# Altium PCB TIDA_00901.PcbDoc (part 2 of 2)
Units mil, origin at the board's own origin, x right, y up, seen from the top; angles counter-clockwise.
Board outline 2500 x 2500 mil, 4 copper layers (Top Layer, GND, PVDD, Bottom Layer), stack 59.2 mil thick; 113 components, 73 nets, 335 pads, 307 vias.
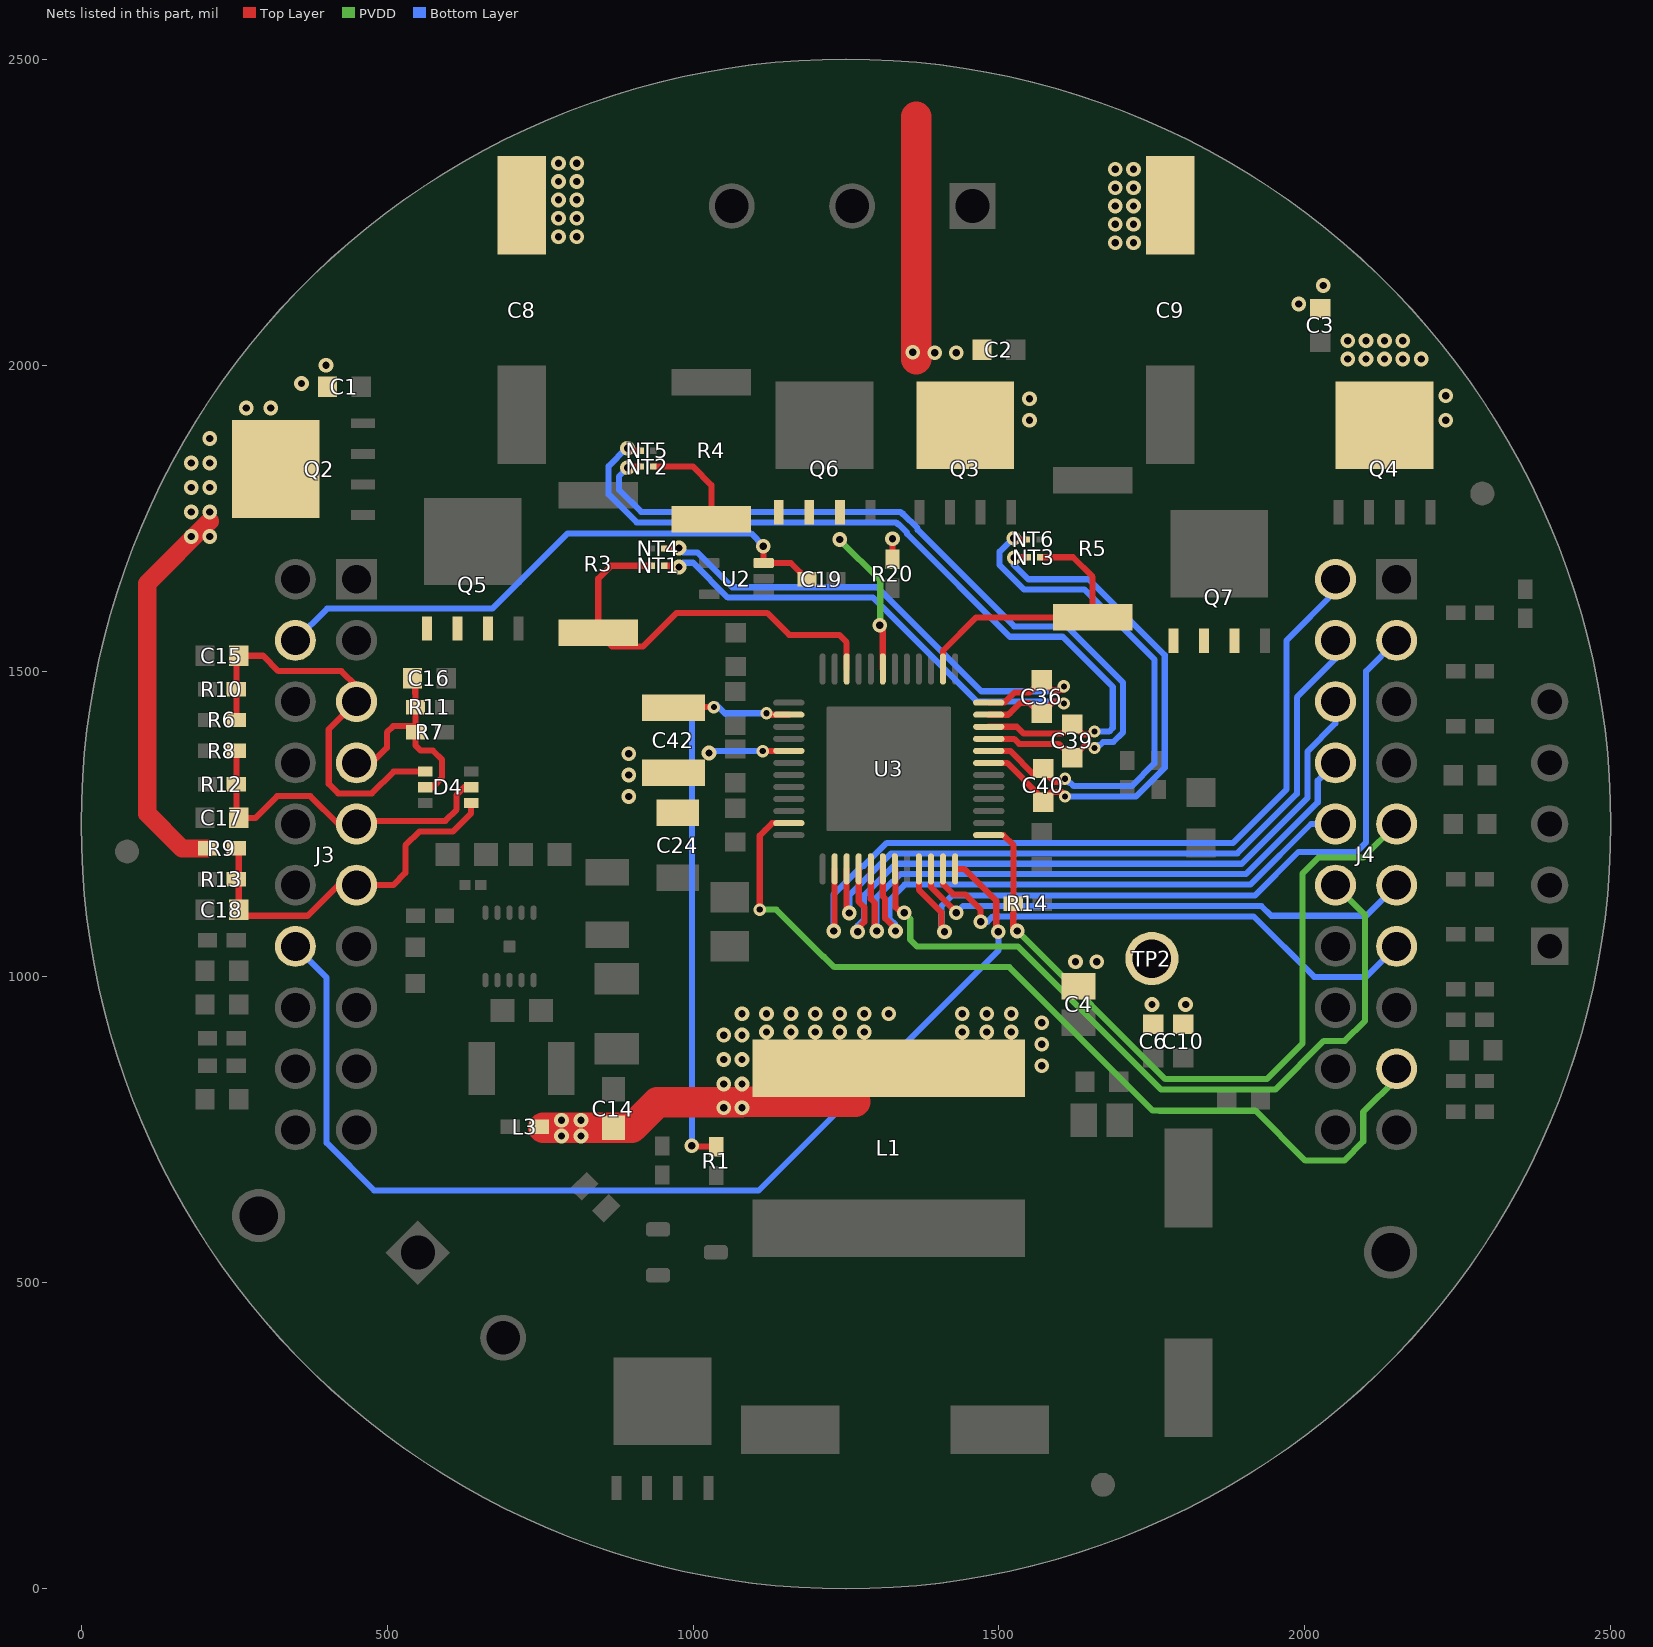
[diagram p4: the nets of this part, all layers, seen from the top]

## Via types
v1: diameter 24, hole 12, Top Layer to Bottom Layer, tented both sides, 267 vias
v2: diameter 19.68, hole 7.87, Top Layer to Bottom Layer, 29 vias
v3: diameter 20, hole 10, Top Layer to Bottom Layer, tented both sides, 11 vias

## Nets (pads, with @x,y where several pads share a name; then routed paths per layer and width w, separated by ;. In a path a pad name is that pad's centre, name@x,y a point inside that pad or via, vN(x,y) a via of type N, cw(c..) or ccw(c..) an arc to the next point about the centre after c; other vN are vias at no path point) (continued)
PVDD: C1.1 C2.1 C3.1 C4.1 C6.1 C8.1 C9.1 C10.1 C14.1 C24.2 C42.2 L1.2 L3.1 Q2.5 Q3.5 Q4.5 R9.2 R20.2 TP2.1 U3.41 | length 1808.1
  Top Layer w10: v3(1114,1369) 1114.53,1369.53 U3.41@1156.61,1369.53 ; R20.2@1326,1682.62 v1(1326,1716)
  Top Layer w20: 1265.09,796 L1.2@1320,850.91
  Top Layer w30: R9.2@206.38,1210 165,1210 108,1267 108,1643 210,1745
  Top Layer w50: L3.1@755.62,753.5 C14.1@870,753.5 900.07,753.5 941.56,795 1079,795 1080,796 1265.09,796 ; 1365,2010 1365,2405.67
  Bottom Layer w10: v1(1026,1366) 1029,1369 v3(1114,1369)
  other v1: 785,740 817,740 785,766 817,766 1050,786 1080,786 1050,825 1080,825 1570,855 1050,865 1080,865 1570,890 1050,905 1080,905 1120,910 1160,910 1200,910 1240,910 1280,910 1440,910 1480,910 1520,910 1570,925 1080,940 1120,940 1160,940 1200,940 1240,940 1280,940 1320,940 1440,940 1480,940 1520,940 1750,955 1805,955 1625,1025 1660,1025 895,1295 895,1330 895,1365 180,1720 210,1720 180,1760 210,1760 180,1800 210,1800 180,1840 210,1840 210,1880 1550,1910 2230,1910 270,1930 310,1930 1550,1945 2230,1950 360,1970 400,2000 2070,2010 2100,2010 2130,2010 2160,2010 2190,2010 1395,2020 1430,2020 1359,2021 2070,2040 2100,2040 2130,2040 2160,2040 1990,2100 2030,2130 1690,2200 1720,2200 780,2210 810,2210 1690,2230 1720,2230 780,2240 810,2240 1690,2260 1720,2260 780,2270 810,2270 1690,2290 1720,2290 780,2300 810,2300 1690,2320 1720,2320 780,2330 810,2330
PWM_AH: J4.2 U3.2 | length 1349.9
  Top Layer w10: v1(1230,1075) 1231.42,1076.42 U3.2@1231.42,1176.61
  Bottom Layer w10: v1(1230,1075) 1230,1135 1276.4,1181.4 1279.27,1181.4 1316.88,1219 1882.58,1219 1970,1306.42 1970,1550 2050,1630 J4.2@2050,1650
PWM_AL: J4.4 U3.3 | length 1186.3
  Top Layer w10: U3.3@1251.1,1176.61 1251.1,1108.9 v1(1255.55,1104.45) v1@1260,1100
  Bottom Layer w10: v1(1255.55,1104.45) 1255.55,1133.63 1323.92,1202 1889.62,1202 1987,1299.38 1987,1457 2050,1520 J4.4@2050,1550
PWM_BH: J4.6 U3.4 | length 1141.9
  Top Layer w10: v1(1268.94,1074) 1268.94,1078.94 1280,1090 1280,1113.94 1270.79,1123.15 U3.4@1270.79,1176.61
  Bottom Layer w10: v1(1268.94,1074) 1268.94,1083.9 1279.55,1094.51 1279.55,1133.59 1330.96,1185 1896.66,1185 2004,1292.34 2004,1368.3 2050,1414.3 J4.6@2050,1450
PWM_BL: J4.8 U3.5 | length 1026.1
  Top Layer w10: U3.5@1290.47,1176.61 1290.47,1127.51 1297,1120.98 1297,1082.96 1296.55,1082.51 v1@1296.55,1070.45
  Bottom Layer w10: v1(1300,1075) 1300,1130 1326.28,1156.28 1327.24,1156.28 1338.96,1168 1903.7,1168 2021,1285.3 2021,1321 J4.8@2050,1350
PWM_CH: J4.10 U3.6 | length 945.8
  Top Layer w10: U3.6@1310.16,1176.61 1310.16,1131.87 1314,1128.02 1314,1096 1331,1079 v1(1331,1075)
  Bottom Layer w10: v1(1331,1075) 1331,1085.06 1321,1095.06 1321,1124.94 1331,1134.94 1331,1136 1346,1151 1911,1151 2010,1250 J4.10@2050,1250
PWM_CL: J4.12 U3.7 | length 1256.7
  Top Layer w10: U3.7@1329.84,1176.61 1331,1175.46 1331,1114 v1@1340,1105
  PVDD w10: v1(1345,1105) 1355,1095 1355,1061 1366,1050 1530.96,1050 1764.96,816 1951.7,816 2031.17,895.46 2065.46,895.46 2098,928 2098,1102 J4.12@2050,1150
PWRGD: J4.9 R14.1 U3.13 | length 1247.5
  Top Layer w10: U3.13@1483.39,1231.73 1507.27,1231.73 1524,1215 1524,1120.62 R14.1@1523.38,1120 1523.38,1081.62 v1(1530,1075)
  PVDD w10: v1(1530,1075) 1530,1073 1532,1073 1772,833 1938,833 1996,891 1996,1169.02 2022.44,1195.46 2095.46,1195.46 J4.9@2150,1250
S1_N: C36.1 NT1.1 U3.23 | length 900.1
  Top Layer w10: NT1.1@953,1672 975,1672 v1(977,1670) ; U3.23@1483.39,1428.58 1514.67,1428.58 1516.99,1430.9 1517.79,1430.9 1534.89,1448 1549.44,1448 C36.1@1570,1427.44 ; C36.1@1570,1430.44 1589.06,1449.5 1603.5,1449.5 v3(1606,1447)
  Bottom Layer w10: v1(977,1670) 984,1677 1000,1677 1057,1620 1294.21,1620 1464.21,1450 1603,1450 v3(1606,1447)
S1_P: C36.2 NT4.1 U3.24 | length 903.3
  Top Layer w10: NT4.1@953,1700 976,1700 v1(977,1701) ; U3.24@1483.39,1448.27 1508.73,1448.27 1525.46,1465 1550,1465 1553.24,1468.24 1567.56,1482.56 C36.2@1570,1482.56 ; C36.2@1570,1485.56 1586.56,1469 1606,1469 v3(1606,1475)
  Bottom Layer w10: v1(977,1701) 984,1694 1007.04,1694 1064.04,1637 1301.25,1637 1471.25,1467 1594.89,1467 1596.89,1469 1597,1469 1603,1475 v3(1606,1475)
S2_N: C39.1 NT2.1 U3.21 | length 1356.1
  Top Layer w10: v1(893,1832) 895,1834 NT2.1@915,1834 ; U3.21@1483.39,1389 U3.21@1483.39,1389.21 1524.75,1389.21 1532.96,1381 1597.44,1381 C39.1@1620,1358.44 1639.06,1377.5 1652.5,1377.5 v3(1656,1374)
  Bottom Layer w10: v1@891.5,1833.5 v1(893,1832) 879,1818 879,1796 915,1760 1339,1760 1342,1757 1342.98,1757 1367,1732.98 1367,1731 1525,1573 1611.04,1573 1703,1481.04 1703,1399.96 1687.04,1384 1670.11,1384 1665.11,1379 1661,1379 v3(1656,1374)
S2_P: C39.2 NT5.1 U3.22 | length 1360.7
  Top Layer w10: v1(893,1864) 897,1860 NT5.1@915,1860 ; U3.22@1483.39,1408.9 1529.1,1408.9 1540,1398 1604.44,1398 C39.2@1620,1413.56 1637.56,1396 1651,1396 v3(1656,1401)
  Bottom Layer w10: v1(893,1864) 891.06,1864 862,1834.94 862,1788.96 907.96,1743 1331.96,1743 1334.96,1740 1335.94,1740 1350,1725.94 1350,1723.96 1517.96,1556 1604,1556 1686,1474 1686,1407 1680,1401 v3(1656,1401)
S3_N: C40.1 NT3.1 U3.19 | length 876
  Top Layer w10: U3.19@1483.39,1349.84 1513.27,1349.84 1567,1296.11 1567,1290.44 C40.1@1572,1285.44 1577,1290.44 1577,1293.5 1585.5,1302 1603,1302 1608,1297 v3(1608,1295) ; v1(1525,1685) 1526,1686 NT3.1@1547,1686
  Bottom Layer w10: v1(1525,1685) 1524,1684 1524,1674.04 1548.04,1650 1647.04,1650 1771,1526.04 1771,1341.96 1724.04,1295 v3(1608,1295)
S3_P: C40.2 NT6.1 U3.20 | length 888.1
  Top Layer w10: U3.20@1483.39,1369.53 1518.47,1369.53 1558,1330 1561.44,1330 C40.2@1572,1340.56 1577,1335.56 1577,1332.5 1590.5,1319 1603,1319 v3(1608,1324) ; v1(1524,1717) 1526,1715 NT6.1@1546,1715
  Bottom Layer w10: v1(1524,1717) 1523.06,1717 1501,1694.94 1501,1673 1541,1633 1640,1633 1754,1519 1754,1349 1717,1312 1622.11,1312 1617.11,1317 1615,1317 v3(1608,1324)
SCLK: J3.14 U3.12 | length 1813.8
  Top Layer w10: U3.12@1428.27,1176.61 1443.39,1176.61 1495.63,1124.37 1495.63,1079.37 1495,1078.74 1499,1074.74 v1@1498.26,1074 ; v1@1494.26,1070 v1@1498.26,1074 ; v1(1499,1074) v1@1498.26,1074
  Bottom Layer w10: J3.14@350,1050 401,999 401,729 479,651 1107.04,651 1397,940.96 ; 1397,941 1499,1043 v1(1499,1074)
SCS: J4.3 U3.9 | length 1251.7
  Top Layer w10: U3.9@1369.21,1176.61 1369.21,1142.79 1406,1106 1406,1079 v1(1411,1074)
  Bottom Layer w10: v1(1411,1074) 1406,1079 1406,1115.92 1423.08,1133 1918,1133 1989.54,1204.54 2084.54,1204.54 2100,1220 2100,1500 J4.3@2150,1550
SDI: J4.11 U3.10 | length 840.5
  Top Layer w10: U3.10@1388.9,1176.61 1388.9,1147.14 v1@1423,1113.04 ; v1@1423,1113 1430,1106 v1(1430,1105)
  Bottom Layer w10: v1(1430,1105) 1441,1116 1929,1116 1945,1100 2100,1100 J4.11@2150,1150
SDO: J4.13 U3.11 | length 869.2
  Top Layer w10: U3.11@1408.58,1176.61 1408.58,1151.5 1425.08,1135 1445,1135 1470,1110 v1(1470,1090)
  Bottom Layer w10: v1(1470,1090) 1481.06,1090 1490.06,1099 1916,1099 2015,1000 2100,1000 J4.13@2150,1050
SL_A: NT1.2 Q5.1 Q5.2 Q5.3 R3.2 U3.34 | length 686.7
  Top Layer w10: NT1.2@933,1672 866,1672 845,1651 R3.2@845,1562.8 867.8,1540 918,1540 973,1595 1120.94,1595 1156.94,1559 1238.98,1559 1251.1,1546.87 U3.34@1251.1,1503.39
SL_B: NT2.2 Q6.1 Q6.2 Q6.3 R4.2 U3.31 | length 404.4
  Top Layer w10: NT2.2@935,1834 1000,1834 1030,1804 R4.2@1030,1747.8 ; U3.31@1310.16,1503.39 v1@1310.16,1568.84
  PVDD w10: v1(1240,1715) 1240,1714 1306,1648 1306,1579.96 1310.96,1575 v1(1305,1575)
SL_C: NT3.2 Q7.1 Q7.2 Q7.3 R5.2 U3.26 | length 462.5
  Top Layer w10: U3.26@1408.58,1503.39 1408.58,1533.58 1462.8,1587.8 R5.2@1653,1587.8 1653,1654 1621,1686 NT3.2@1567,1686
TEMP: C19.1 J3.4 U2.3 | length 956.4
  Top Layer w10: v1(1115,1704) 1115.29,1703.71 U2.3@1115.29,1676.59 1159.79,1676.59 C19.1@1186.38,1650
  Bottom Layer w10: J3.4@350,1550 402,1602 672,1602 795,1725 1095,1725 1115,1705 v1(1115,1704)
VCPH: C42.1 R1.1 U3.38 | length 985
  Top Layer w10: C42.1@964,1441.15 1033.85,1441.15 v3(1034,1441) ; v1(998,724) 999.38,722.62 R1.1@1038,722.62 ; v3(1120,1431) v3@1120,1435 ; v3@1122.42,1428.58 U3.38@1156.61,1428.58
  Bottom Layer w10: v1(998,724) 998,1422 1017,1441 v3(1034,1441) 1038,1445 1053,1430 1054,1431 v3(1120,1431)
VSEN_A: C15.1 D4.1 J3.5 R6.1 R10.2 | length 677.4
  Top Layer w10: R6.1@253.62,1420 253.62,1521.06 C15.1@257.56,1525 297.44,1525 322.44,1500 425,1500 450,1475 J3.5@450,1450 404.54,1404.54 404.54,1315.46 420,1300 475,1300 510.59,1335.59 D4.1@562.6,1335.59
VSEN_B: C16.1 D4.2 J3.7 R7.1 R11.2 | length 355.7
  Top Layer w10: J3.7@450,1350 475,1350 499.61,1374.61 499.61,1399.61 510,1410 R7.1@546.38,1410 ; C16.1@546,1482 546.22,1441 R7.1@546.38,1410 ; D4.2@562.6,1310 574,1310 579.32,1315.32 579.38,1315.32 586.41,1322.35 586.41,1322.41 590,1326 590,1355 575,1370 555,1370 546.38,1378.62 R7.1@546.38,1400 R7.1@546.38,1410
VSEN_C: C17.1 D4.5 J3.9 R8.1 R12.2 | length 563.9
  Top Layer w10: R8.1@253.62,1370 253.62,1263.94 C17.1@257.56,1260 285,1260 320.46,1295.46 374.54,1295.46 420,1250 J3.9@450,1250 455,1255 595,1255 613.59,1273.59 613.59,1297.65 620.62,1304.68 620.68,1304.68 626,1310 D4.5@637.4,1310
VSEN_PVDD: C18.1 D4.4 J3.11 R9.1 R13.2 | length 588.3
  Top Layer w10: R9.1@253.62,1210 257.56,1206.06 C18.1@257.56,1110 267.56,1100 370,1100 420,1150 J3.11@450,1150 510,1150 530,1170 530,1215 553,1238 608,1238 637.4,1267.4 637.4,1274.41
WAKE: J4.17 U3.47 | length 1487.7
  Top Layer w10: v3(1109,1110) 1109,1230.96 1118,1239.96 1125.03,1247 1129.46,1251.42 U3.47@1156.61,1251.42
  PVDD w10: v3(1109,1110) 1136,1110 1213,1033 1213.96,1033 1230.96,1016 1516.88,1016 1750.88,782 1762,782 1762.7,781.3 1919.49,781.3 2000.79,700 2064.3,700 2095.46,731.17 2095.46,779.46 2150,834 J4.17@2150,850
pads on no net: FID1.1 FID2.1 FID3.1 J3.1 J3.8 J3.10 J3.12 J3.16 J3.18 J3.19 J3.20 J4.7 J4.18 J4.19 J4.20 U4.6

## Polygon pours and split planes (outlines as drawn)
MOT_A on Bottom Layer "Bottom Layer-No Net" (solid, remove dead copper, pour order 9): 920,2330 1160,2330 1160,2130 930,1900 860,1900 820,1900 770,1850 770,1625 499.21,1625 499.21,1685.79 475,1710 270,1710 270,1940 660,2330
MOT_C on Bottom Layer "Bottom Layer-No Net 1" (solid, remove dead copper, pour order 10): 1390,2330 1810,2330 1835,2305 2175,1965 2175,1710 2035,1710 1995,1670 1995,1575 1705,1575 1700,1580 1640,1640 1640,1820 1640,1825 1390,2075
GND on Bottom Layer "PVDD-No Net" (solid, remove dead copper, pour order 14): 149,1840 202.77,1920.47 215,1950 244,1992 278,2035 315,2080 405,2172 490,2243 555.54,2289.34 665,2356 795,2415 909,2453 979,2470 1099,2491 1179.88,2498.53 1279,2500 1346,2497 1447,2485 1528.26,2469.14 1629.6,2440.97 1710,2412 1792.57,2376.65 1858,2343 1977,2268 2099,2173 2182.42,2083.26 2237,2019 2314,1909 2384,1777 2451.62,1596.18 2480,1477 2497,1338 2498.53,1179.88 2492,1098 2471,978 2405.3,771.46 2344.46,645.11 2269.85,526.38 2197,435 2108.75,341.67 1973.62,230.15 1861,160 1752,105 1625,57 1493.86,24.02 1390.01,7.37 1337,3 1172,2 1040.53,17.18 903.82,48.38 748,105 665,146 526.38,230.15 443.53,294.95 334,398 263,483 166,627 111,727 59.03,870.4 28,989 7.37,1109.99 0,1263 24.02,1493.86 48.38,1596.18 86,1707 139.44,1823.73
PVDD on Top Layer "Top Layer-No Net" (solid, remove dead copper, pour order 8): 61.08,1640 98,1736 123.35,1792.57 169,1878 223,1963 272.33,2029.67 349,2117 391.25,2158.33 489,2242 547,2284 676.27,2360.56 771.46,2405.3 870.4,2440.97 957,2466 1040.53,2482.82 1161,2496 1274,2501 1371,2495 1509,2474 1647,2437 1752,2397 1885.09,2326.64 1964,2276 2024,2232 2108.75,2158.33 2145,2124 2198,2065 2260,1986 2308.82,1915.3 2352,1841 2367,1809 1995,1810 1995,2070 1885,2180 1665,2180 960,2180 865.5,2117 615,2117 615,1640
GND on Top Layer "PVDD-No Net" (solid, remove dead copper, pour order 13): 149,1840 202.77,1920.47 215,1950 244,1992 278,2035 315,2080 405,2172 490,2243 555.54,2289.34 665,2356 795,2415 909,2453 979,2470 1099,2491 1179.88,2498.53 1279,2500 1346,2497 1447,2485 1528.26,2469.14 1629.6,2440.97 1710,2412 1792.57,2376.65 1858,2343 1977,2268 2099,2173 2182.42,2083.26 2237,2019 2314,1909 2384,1777 2451.62,1596.18 2480,1477 2497,1338 2498.53,1179.88 2492,1098 2471,978 2405.3,771.46 2344.46,645.11 2269.85,526.38 2197,435 2108.75,341.67 1973.62,230.15 1861,160 1752,105 1625,57 1493.86,24.02 1390.01,7.37 1337,3 1172,2 1040.53,17.18 903.82,48.38 748,105 665,146 526.38,230.15 443.53,294.95 334,398 263,483 166,627 111,727 59.03,870.4 28,989 7.37,1109.99 0,1263 24.02,1493.86 48.38,1596.18 86,1707 139.44,1823.73
PVDD on PVDD "PVDD-No Net" (solid, remove dead copper, pour order 12): 149,1840 202.77,1920.47 215,1950 244,1992 278,2035 315,2080 405,2172 490,2243 555.54,2289.34 665,2356 795,2415 909,2453 979,2470 1099,2491 1179.88,2498.53 1279,2500 1346,2497 1447,2485 1528.26,2469.14 1629.6,2440.97 1710,2412 1792.57,2376.65 1858,2343 1977,2268 2099,2173 2182.42,2083.26 2237,2019 2314,1909 2384,1777 2451.62,1596.18 2480,1477 2497,1338 2498.53,1179.88 2492,1098 2471,978 2405.3,771.46 2344.46,645.11 2269.85,526.38 2197,435 2108.75,341.67 1973.62,230.15 1861,160 1752,105 1625,57 1493.86,24.02 1390.01,7.37 1337,3 1172,2 1040.53,17.18 903.82,48.38 748,105 665,146 526.38,230.15 443.53,294.95 334,398 263,483 166,627 111,727 59.03,870.4 28,989 7.37,1109.99 0,1263 24.02,1493.86 48.38,1596.18 86,1707 139.44,1823.73
GND on GND "PVDD-No Net" (solid, remove dead copper, pour order 11): 149,1840 202.77,1920.47 215,1950 244,1992 278,2035 315,2080 405,2172 490,2243 555.54,2289.34 665,2356 795,2415 909,2453 979,2470 1099,2491 1179.88,2498.53 1279,2500 1346,2497 1447,2485 1528.26,2469.14 1629.6,2440.97 1710,2412 1792.57,2376.65 1858,2343 1977,2268 2099,2173 2182.42,2083.26 2237,2019 2314,1909 2384,1777 2451.62,1596.18 2480,1477 2497,1338 2498.53,1179.88 2492,1098 2471,978 2405.3,771.46 2344.46,645.11 2269.85,526.38 2197,435 2108.75,341.67 1973.62,230.15 1861,160 1752,105 1625,57 1493.86,24.02 1390.01,7.37 1337,3 1172,2 1040.53,17.18 903.82,48.38 748,105 665,146 526.38,230.15 443.53,294.95 334,398 263,483 166,627 111,727 59.03,870.4 28,989 7.37,1109.99 0,1263 24.02,1493.86 48.38,1596.18 86,1707 139.44,1823.73

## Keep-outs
Keep-Out Layer:
  lines w20: -10,1250 cw(c1250,1250) 1250,2510 cw(c1250,1250) 2510,1250 cw(c1250,1250) 1250,-10 cw(c1250,1250) -10,1250 ; 0,1250 cw(c1250,1250) 1250,2500 cw(c1250,1250) 2500,1250 cw(c1250,1250) 1250,0 cw(c1250,1250) 0,1250
  text ".Layer_Name" at 577,-858.49 h60

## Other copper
Top Layer:
  region net 3.3V: 930,1635 930,1610 1038.69,1610 1049.35,1620.65 1049.35,1685 1010,1685 1010,1669.06 975.94,1635
  region net GND: 2210,900 2270,900 2270,860 2210,860
  region net 3.3V: 1555,1060 1595,1060 1605,1070 1605,1100 1555,1100
  pour cut-out: 880,1643 975,1643 975,1723 880,1723
  pour cut-out: 990,1890 895,1890 895,1810 990,1810
  region net GND: 715,985.17 715,1020 750,1020 750,975 725.17,975
  region net GND: 625,1075 625,1090 655,1120 665,1120 665,1080
  region net GND: 440,1990 440,1935 520,1935 520,1990
  region net NetC33_1: 705,1010 675,1010 675,977.27 625,927.27 625,785 666.81,743.19 720,743.19 720,958.54 705,973.54
  region net 3.3V: 1584.5,1099.5 1540,1055 1215,1055 1185,1085 1185,1235 1130,1235 1130,1106.82 1108.18,1085 850,1085 795,1085 795,988 828,955 920,955 965,1000 1175,1000 1550,1000 1649.5,1099.5
  region net 3.3V: 1875,1260 1740,1260 1725,1275 1725,1325 1695,1325 1695,1195 1645,1145 1555,1145 1555,1095 1840,1095 1875,1130
  region net MOT_C: 2175,1800 1735,1800 1735,1657.06 1792.06,1600 1980,1600 1980,1679.41 2025.59,1725 2175,1725
  region net PVDD: 1375,1810 1340,1845 1340,2050 1340,2113.62 1389.39,2113.62 1453.01,2050 1500,2050 1500,2000 1555,2000 1575,1980 1575,1810
  region net MOT_A: 415.79,1874.21 415.79,1764.21 500,1680 500,1619.21 760.79,1619.21 760.79,1814.21 610.79,1814.21 550.79,1874.21
  region net PVDD: 1036,1380 880,1380 880,1264 909,1235 1036,1235
  region net NetQ1_3: 1010,190 1010,135 1075,135 1075,190
  region net NetQ1_3: 995,695 995,465 1030,465 1065,500 1065,695
  region net NetQ1_1: 980,695 933,695 905,667 905,559.21 919.21,545 980,545
  region net NetD1_2: 865,654.97 832,621.97 832,518 885,465 970.39,465 970.39,535 915,535 895,555 895,625
  region net NetC5_1: 830,445 830,235 855,210 1315,210 1530,425 1810,425 1900,515 1900,830 1735,830 1718,847 1675,847 1675,730 1640,695 1075,695 1075,480 1040,445
  region net NetD1_1: 1000,200 1000,135 817,135 570,382 570,475 785,690 845,690 865,670 820,625 820,230 850,200
  region net PVDD: 1830,1025 1830,907 1728,907 1674,961 1587,961 1585,959 1585,837.72 1517.28,770 1035,770 1035,920 1105,990 1550,990 1640,1080 1775,1080
  region net SL_C: 1580,1610 1580,1560 1680,1460 1840,1460 1915,1535 1915,1575 1785,1575 1750,1610
  region net SL_B: 920,1795 920,1723 1133.77,1723 1177.77,1679 1271,1679 1271,1795 1110,1795
  region net SL_A: 556.06,1595 556.06,1520 620,1520 685,1455 840,1455 928,1543 928,1585 770,1585 725,1540 705,1540 695,1550 695,1595
  pour cut-out: 1580,1810 1580,1610 1725,1610 1725,1810
  pour cut-out: 780,1765 780,1584.76 910,1584.76 910,1765
  pour cut-out: 968.98,1950 968.98,1770 1102,1770 1102,1950
  region net MOT_A: 1175,2330 1020,2330 890,2200 890,2030 1060,2030 1175,2145
  region net MOT_C: 1404.45,2330 1404.45,2118.7 1463.15,2060 1655,2060 1655,2230 1555,2330
  region net MOT_B: 1185,2330 1185,2120 1110,2045 1110,1816 1121,1805 1289,1805 1315,1779 1315,1735 1335,1735 1385,1685 1385,1650 1392,1650 1477,1735 1490,1748 1490,1790 1385,1790 1325,1850 1325,2330
  region net SL_B: 1095,1725 1063.32,1693.32 1016.68,1693.32 980,1730 1095,1730
  text ".Layer_Name" at 577,-858.49 h60
Bottom Layer:
  region net NetC5_1: 960,445 960,235 985,210 1315,210 1530.27,425.27 1809.37,425.27 1899.1,515 1900,515 1900,830 1734.91,830 1715.24,849.67 1712.57,847 1675,847 1675,730 1640,695 1175,695 1075,595 1075,480 1040,445
  region net MOT_B: 1200,2330 1200,2135 1110,2045 1110,1816 1121,1805 1370,1805 1325,1850 1325,2330
  text ".Layer_Name" at 577,-858.49 h60

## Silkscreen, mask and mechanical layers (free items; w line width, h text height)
Top Overlay:
  lines w5: 660,1340 660,1365 745,1365 745,1285 660,1285 ; 660,1345 660,1285 ; 660,1240 660,1285 ; 660,1240 655,1245 665,1245 660,1240
  text "TID-00901" at 805,1015 h60
  text ".PCB_Rev" at 1405,1015 h60
  text ".Layer_Name" at 577,-858.49 h60
Bottom Overlay:
  text ".Layer_Name" at 577,-858.49 h60
Top Paste:
  text ".Layer_Name" at 577,-858.49 h60
Bottom Paste:
  text ".Layer_Name" at 577,-858.49 h60
Top Solder:
  text ".Layer_Name" at 577,-858.49 h60
  text ".Layer_Name" at 577,-858.49 h60
Bottom Solder:
  text ".Layer_Name" at 577,-858.49 h60
Drill Guide:
  text ".Layer_Name" at 577,-858.49 h60
M1 Board Outline:
  circle w10: c1250,1250 r1250
  text ".Layer_Name" at 577,-858.49 h60
M2 Board Dimensions:
  rectangle: 0,-275 125,-150
  rectangle: 125,-400 500,-275
  lines w7: 0,-275 1000,-275 ; 125,-400 125,-150 ; 250,-400 250,-150 ; 500,-400 500,-150 ; 750,-400 750,-150 ; 0,-400 1000,-400 1000,-150 0,-150 0,-400
  text ".Layer_Name" at 577,-858.49 h60
M3 3D STEP Top:
  text ".Layer_Name" at 577,-858.49 h60
M4 3D STEP Bottom:
  text ".Layer_Name" at 577,-858.49 h60
M5 Assembly Top:
  lines w10: -292,-930.17 6308,-930.17 ; -292,-726.83 6310,-726.83 ; -292,-523.5 -292,-1133.5 3713,-1133.5 6310,-1133.5 6310,-523.5 -291.5,-523.5 -291.5,-1133.5 1284,-1133.5 ; 2173,-1133.5 2173,-523.5 ; 3440,-726.83 3440,-523.5 ; 4280,-726.83 4280,-523.5 ; 4902,-1140 4902,-937.17
  text "NOTE: Install J3 and J4 on the BOTTOM side of the board" at 88,3446 h60
  text "COMPONENTS MARKED 'DNP' SHOULD NOT BE POPULATED." at 1153.5,-318.5 h60
  text "ASSEMBLY VARIANT:" at 1153,-434 h60
  text ".VariantName" at 2189,-434 h60
  text "PCB VIEWED FROM TOP SIDE" at -228.5,-655.67 h60
  text "BOARD #:" at 2248,-655.67 h60
  text ".PRJ_Number" at 2793.5,-655.67 h60
  text "REV:" at 3638,-655.67 h60
  text ".PCB_Rev" at 3929.5,-655.67 h60
  text "SVN REV:" at 4476,-655.67 h60
  text ".VersionControl_RevNumber" at 4982,-655.67 h60
  text "TID #:" at 2248,-859 h60
  text ".TID" at 2793.5,-859 h60
  text "PLOT NAME =" at -228.5,-1064.34 h60
  text ".plot_File_Name" at 577,-1064.34 h60
  text "GENERATED    :" at 2250,-1064.34 h60
  text ".Print_Date" at 3119.5,-1064.34 h60
  text ".Print_Time" at 3848.5,-1064.34 h60
  text "TEXAS INSTRUMENTS" at 5113,-1064.34 h60
M6 Assembly Bottom:
  lines w10: -292.5,-727.33 6309.5,-727.33 ; -290.5,-930.67 6309.5,-930.67 ; 1115.5,-1140.5 1115.5,-937.67 ; 1737.5,-727.33 1737.5,-524 ; 2577.5,-727.33 2577.5,-524 ; 3844.5,-1134 3844.5,-524 ; 4733.5,-1134 6309,-1134 6309,-524 -292.5,-524 -292.5,-1134 2304.5,-1134 6309.5,-1134 6309.5,-524
  text "COMPONENTS MARKED 'DNP' SHOULD NOT BE POPULATED." at 6102,-318 h60
  text ".VariantName" at 5058,-434 h60
  text "ASSEMBLY VARIANT:" at 6097,-434 h60
  text ".VersionControl_RevNumber" at 1035.5,-656.17 h60
  text "SVN REV:" at 1541.5,-656.17 h60
  text ".PCB_Rev" at 2088,-656.17 h60
  text "REV:" at 2379.5,-656.17 h60
  text ".PRJ_Number" at 3224,-656.17 h60
  text "BOARD #:" at 3769.5,-656.17 h60
  text "PCB VIEWED FROM BOTTOM SIDE" at 6246,-656.17 h60
  text ".TID" at 3224,-859.5 h60
  text "TID #:" at 3769.5,-859.5 h60
  text "TEXAS INSTRUMENTS" at 904.5,-1064.84 h60
  text ".Print_Time" at 2169,-1064.84 h60
  text ".Print_Date" at 2898,-1064.84 h60
  text "GENERATED    :" at 3767.5,-1064.84 h60
  text ".plot_File_Name" at 5440.5,-1064.84 h60
  text "PLOT NAME =" at 6246,-1064.84 h60
M9 Title Sheet:
  drawing of 57 lines, arcs and shapes, not listed
  text "1" at 739.84,8036.5 h70
  text "2" at 3235.5,8036.5 h70
  text "3" at 5724.84,8036.5 h70
  text "4" at 8231.51,8036.5 h70
  text "5" at 10730.5,8036.5 h70
  text "6" at 13235.5,8036.5 h70
  text "A" at -416.5,6893.5 h70
  text "A" at 14383.5,6893.5 h70
  text "B" at -416.5,4513.5 h70
  text "B" at 14383.5,4513.5 h70
  text "C" at -416.5,2138.5 h70
  text "C" at 14383.5,2138.5 h70
  text "PROJECT TITLE:" at 11343.5,277.5 h45
  text ".PRJ_Title" at 11393.5,144.17 h70
  text "DESIGNED FOR:" at 11343.5,-23.5 h45
  text ".PRJ_Customer" at 11393.5,-163.5 h70
  text "D" at -416.5,-231.5 h70
  text "D" at 14383.5,-231.5 h70
  text "FILE NAME:" at 11343.5,-323.5 h45
  text ".PCB_File_Name_No_Path" at 11393.5,-443.5 h70
  text "Texas Instruments (TI) and/or its licensors do not warrant the accuracy or completeness of this specification" at 6374,-605.34 h45
  text "ENGINEER:" at 11343.5,-613.5 h45
  text "LAYOUT BY:" at 12848.5,-613.5 h45
  text "or any information contained therein. TI and/or its licensors do not warrant that this design will meet" at 6329.01,-718 h45
  text ".PRJ_Engineer" at 11393.5,-768.49 h70
  text ".PCB_Layout" at 12899,-768.49 h70
  text "the specifications, will be suitable for your application or fit for any particular purpose, or will operate in" at 6329.01,-830.67 h45
  text ".Layer_Name" at 577,-858.49 h60
  text "ALTIUM DESIGNER VERSION:" at 12848.5,-923.5 h45
  text "an implementation. TI and/or its licensors do not warrant that the design is production worthy. You should" at 6329.01,-943.33 h45
  text "completely validate and test your design implementation to confirm the system functionality for your application." at 6374,-1056 h45
  text ".print_Scale" at 11393.5,-1056.83 h70
  text ".Application_BuildNumber" at 12899,-1056.83 h70
  text "1" at 739.84,-1263.5 h70
  text "2" at 3235.5,-1263.5 h70
  text "3" at 5724.84,-1263.5 h70
  text "4" at 8231.51,-1263.5 h70
  text "5" at 10730.5,-1263.5 h70
  text "6" at 13235.5,-1263.5 h70
M10 Fab Notes:
  drawing of 189 lines, arcs and shapes, not listed
  text "DESIGN INFORMATION" at 12381.02,6028 h60
  text "MIN. TRACK WIDTH:" at 11736.46,5848 h60
  text "8" at 12832.7,5848 h60
  text "MIL" at 12987.46,5848 h60
  text "MIN. CLEARANCE:" at 11736.46,5716 h60
  text "0.2" at 12772.7,5716 h60
  text "mm" at 12987.46,5716 h60
  text "MIN. VIA PAD SIZE:" at 11736.46,5584 h60
  text "24" at 12802.71,5584 h60
  text "MIL" at 12987.46,5584 h60
  text "0.05mm (2MIL)" at 12431.46,5442.29 h60
  text "MINIMUM ANNULAR RING" at 11407.23,5438 h60
  text "EXTERNAL" at 13139.46,5438 h60
  text "PER" at 11607.23,5320 h60
  text "IPC-D-275 CLASS 2 LEVEL C" at 11827.23,5320 h60
  text "MIL, HOLES" at 13315.46,5207.71 h60
  text "+/-" at 12923,5207 h60
  text "+/-" at 13777,5207 h60
  text "REGISTRATION TOLERANCES:" at 11407.23,5202 h60
  text "METAL" at 12607,5202 h60
  text "5" at 13183.2,5202 h60
  text "3" at 14016.2,5202 h60
  text "MIL" at 14132.46,5202 h60
  text "+/-" at 13777,5089 h60
  text "HOLE SIZE TOLERANCE (UNLESS OTHERWISE SPECIFIED):" at 11407.23,5084 h60
  text "3" at 14016.2,5084 h60
  text "MIL" at 14132.46,5084 h60
  text "MATERIAL:" at 11332.46,4874.54 h60
  text "FR-4 High Tg" at 12318.9,4734.21 h60
  text "FR-408" at 11753.46,4725.64 h60
  text "OTHER" at 13241.46,4725.64 h60
  text "X" at 12164,4722 h60
  text "62 MIL (1.6mm) +/-10%" at 12073.56,4562.92 h60
  text "THICKNESS:" at 11407.23,4558.64 h60
  text "X" at 11945.4,4558.64 h60
  text "OTHER" at 13358.46,4558.64 h60
  text "TOLERANCE:" at 11407.23,4400.64 h60
  text "X" at 12246.53,4400.64 h60
  text "ANSI IPC-6012 TYPE 3 CLASS 2" at 12433.48,4400.64 h60
  text "OTHER +/-" at 12433.46,4244.64 h60
  text "BOW & TWIST:" at 11407.23,4087.64 h60
  text "X" at 12246.53,4087.64 h60
  text "ANSI IPC-6012 TYPE 3 CLASS 2" at 12433.48,4087.64 h60
  text "OTHER +/-" at 12433.46,3929.13 h60
  text "DRILLING:" at 11332.46,3790.64 h60
  text "REFERENCE:" at 11407.23,3673.64 h60
  text "X" at 12055.46,3673.64 h60
  text "AS SHOWN" at 12242.46,3673.64 h60
  text "X" at 12956.46,3673.64 h60
  text "NC_DRILL FILES" at 13093.46,3673.64 h60
  text "PTH MIN COPPER THICKNESS:" at 11407.23,3515.64 h60
  text "X" at 12757.46,3515.64 h60
  text "1MIL" at 12894.46,3515.64 h60
  text "OTHER" at 13391.46,3515.64 h60
  text "BOARD FINISH:" at 11332.46,3356.64 h60
  text "SILKSCREEN:" at 11487.68,3238.64 h60
  text "X" at 12436.46,3238.64 h60
  text "TOP" at 12562.46,3238.64 h60
  text "X" at 12946.46,3238.64 h60
  text "BOTTOM" at 13073.46,3238.64 h60
  text "SILKSCREEN COLOR:" at 11487.68,3071.64 h60
  text "X" at 12435.42,3071.64 h60
  text "WHITE" at 12562.46,3071.64 h60
  text "OTHER" at 13073.46,3071.64 h60
  text "X" at 12566.42,2912.44 h60
  text "GREEN" at 12693.46,2912.44 h60
  text "OTHER" at 13311.46,2912.44 h60
  text "SOLDER RESIST COLOR:" at 11487.68,2901.64 h60
  text "X" at 12566.42,2742.44 h60
  text "MATTE" at 12693.46,2742.44 h60
  text "SEMI-GLOSS" at 13311,2741.8 h60
  text "IMMERSION GOLD (ENIG)" at 12393.46,2553.92 h60
  text "ENEPIG" at 13731,2550.64 h60
  text "SURFACE FINISH:" at 11332.46,2549.64 h60
  text "X" at 12206.51,2549.64 h60
  text "IMM. TIN/SILVER OR EQUIV" at 11662,2392.64 h60
  text "OTHER" at 13093.46,2392.64 h60
  text "ARRAY/PANEL:" at 11332.46,2213.64 h60
  text "CUT AND TRIM PER M1 BOARD OUTLINE" at 12393.46,2209.35 h60
  text "N.C. ROUTE" at 12393.46,2057.64 h60
  text "X" at 13072.46,2057.64 h60
  text "V. SCORE" at 13259.46,2057.64 h60
  text "CERTIFICATION:" at 11332.46,1920.64 h60
  text "MATERIALS AND WORKMANSHIP FOR ALL PCBS" at 12057.46,1920.64 h60
  text "TO MEET OR EXCEED THE REQUIREMENTS OF:" at 12057.46,1822.64 h60
  text "X" at 11683.96,1686.13 h60
  text "ANSI IPC-A-600F CLASS ->" at 11822.96,1686.13 h60
  text "X" at 13462.02,1686.13 h60
  text "2" at 13580.96,1686.14 h60
  text "1" at 13265.96,1684.64 h60
  text "3" at 13934.96,1684.64 h60
  text "X" at 11686.02,1526.64 h60
  text "UL 94V-0" at 11822.96,1526.64 h60
  text "X" at 12498.02,1526.64 h60
  text "RoHS" at 12634.96,1526.64 h60
  text "OTHER" at 13279.36,1526.64 h60
  text "PER ORDER" at 13676.42,1526.64 h60
  text "ADDITIONAL REQUIREMENTS:" at 11332.46,1385.64 h60
  text "MICROSECTION:" at 11407.23,1270.64 h60
  text "YES" at 12312.96,1270.64 h60
  text "REQUIRED" at 13174.46,1114.49 h60
  text "BARE BOARD ELEC. TEST:" at 11407.23,1111.64 h60
  text "NONE" at 12712.96,1111.64 h60
  text "X" at 13047.46,1111.64 h60
  text "PER ORDER" at 13766.46,1111.64 h60
  text "MANUFACTURER'S UL:" at 11407.23,954.64 h60
  text "RAIL" at 12572.96,950.35 h60
  text "METAL" at 13064.77,950.35 h60
  text "X" at 13440,950 h60
  text "SILK" at 13576.46,950.35 h60
  text ".Layer_Name" at 577,-858.49 h60
M11 Gerber Information:
  lines w10: -292,-930.17 6308,-930.17 ; -292,-726.83 6310,-726.83 ; -292,-523.5 -292,-1133.5 3713,-1133.5 6310,-1133.5 6310,-523.5 -291.5,-523.5 -291.5,-1133.5 1284,-1133.5 ; 2173,-1133.5 2173,-523.5 ; 3440,-726.83 3440,-523.5 ; 4280,-726.83 4280,-523.5 ; 4902,-1140 4902,-937.17
  text "ALL ARTWORK VIEWED FROM TOP SIDE" at -228.5,-655.67 h60
  text "BOARD #:" at 2248,-655.67 h60
  text ".PRJ_Number" at 2793.5,-655.67 h60
  text "REV:" at 3638,-655.67 h60
  text ".PCB_Rev" at 3929.5,-655.67 h60
  text "SVN REV:" at 4476,-655.67 h60
  text ".VersionControl_RevNumber" at 4982,-655.67 h60
  text "LAYER NAME =" at -228.5,-858.49 h60
  text "TID #:" at 2248,-859 h60
  text ".TID" at 2793.5,-859 h60
  text "PLOT NAME =" at -228.5,-1064.34 h60
  text ".plot_File_Name" at 577,-1064.34 h60
  text "GENERATED    :" at 2250,-1064.34 h60
  text ".Print_Date" at 3119.5,-1064.34 h60
  text ".Print_Time" at 3848.5,-1064.34 h60
  text "TEXAS INSTRUMENTS" at 5113,-1064.34 h60
M12 Stackup:
  drawing of 295 lines, arcs and shapes, not listed
  text "Layer" at 9760,7800 h60
  text "Name" at 10169.91,7800 h60
  text "Material" at 11109.65,7800 h60
  text "Thickness" at 11969.42,7800 h60
  text "Constant" at 12619.26,7800 h60
  text "Board Layer Stack" at 13189.12,7800 h60
  text "1" at 9760,7680 h60
  text "Top Overlay" at 10169.91,7680 h60
  text "2" at 9760,7560 h60
  text "Top Solder" at 10169.91,7560 h60
  text "Solder Resist" at 11109.65,7560 h60
  text "0.40mil" at 11969.42,7560 h60
  text "3.5" at 12619.26,7560 h60
  text "3" at 9760,7440 h60
  text "Top Layer" at 10169.91,7440 h60
  text "Copper" at 11109.65,7440 h60
  text "2.80mil" at 11969.42,7440 h60
  text "4" at 9760,7320 h60
  text "Dielectric1" at 10169.91,7320 h60
  text "FR-4" at 11109.65,7320 h60
  text "10.00mil" at 11969.42,7320 h60
  text "4.2" at 12619.26,7320 h60
  text "5" at 9760,7200 h60
  text "Signal Layer 1" at 10169.91,7200 h60
  text "Copper" at 11109.65,7200 h60
  text "2.80mil" at 11969.42,7200 h60
  text "6" at 9760,7080 h60
  text "Dielectric 3" at 10169.91,7080 h60
  text "FR-4" at 11109.65,7080 h60
  text "28.00mil" at 11969.42,7080 h60
  text "4.2" at 12619.26,7080 h60
  text "7" at 9760,6960 h60
  text "Signal Layer 2" at 10169.91,6960 h60
  text "Copper" at 11109.65,6960 h60
  text "2.80mil" at 11969.42,6960 h60
  text "8" at 9760,6840 h60
  text "Dielectric 2" at 10169.91,6840 h60
  text "FR-4" at 11109.65,6840 h60
  text "10.00mil" at 11969.42,6840 h60
  text "4.2" at 12619.26,6840 h60
  text "9" at 9760,6720 h60
  text "Bottom Layer" at 10169.91,6720 h60
  text "Copper" at 11109.65,6720 h60
  text "2.80mil" at 11969.42,6720 h60
  text "10" at 9760,6600 h60
  text "Bottom Solder" at 10169.91,6600 h60
  text "Solder Resist" at 11109.65,6600 h60
  text "0.40mil" at 11969.42,6600 h60
  text "3.5" at 12619.26,6600 h60
  text "11" at 9760,6480 h60
  text "Bottom Overlay" at 10169.91,6480 h60
  text ".Layer_Name" at 577,-858.49 h60
M13 Component Bodies Top:
  text ".Layer_Name" at 577,-858.49 h60
M14 Component Bodies Bottom:
  text ".Layer_Name" at 577,-858.49 h60
M15 Courtyards Top:
  text ".Layer_Name" at 577,-858.49 h60
M16 Courtyards Bottom:
  text ".Layer_Name" at 577,-858.49 h60
Drill Drawing:
  circle w1: c3142.72,1571.04 r24.89
  lines w1: 3117.83,650.24 3117.83,662.68 3130.27,675.12 3117.83,687.57 3117.83,700.01 3130.27,700.01 3142.72,687.57 3155.16,700.01 3167.6,700.01 3167.6,687.57 3155.16,675.12 3167.6,662.68 3167.6,650.24 3155.16,650.24 3142.72,662.68 3130.27,650.24 3117.83,650.24 ; 3117.83,812 3130.27,812 3130.27,799.56 3155.16,799.56 3155.16,812 3167.6,812 3167.6,836.89 3155.16,836.89 3155.16,849.33 3130.27,849.33 3130.27,836.89 3117.83,836.89 3117.83,812 ; 3117.83,948.88 3142.72,961.32 3167.6,948.88 3155.16,973.76 3167.6,998.65 3142.72,986.21 3117.83,998.65 3130.27,973.76 3117.83,948.88 ; 3117.83,1110.64 3130.27,1110.64 3142.72,1098.2 3155.16,1110.64 3167.6,1110.64 3155.16,1123.08 3167.6,1135.53 3155.16,1135.53 3142.72,1147.97 3130.27,1135.53 3117.83,1135.53 3130.27,1123.08 3117.83,1110.64 ; 3117.83,1297.29 3167.6,1297.29 3142.72,1247.52 3117.83,1297.29 ; 3117.83,1396.84 3167.6,1396.84 3167.6,1446.61 3117.83,1446.61 3117.83,1396.84
  lines w12: 3050,605.44 5168.02,605.44 ; 3050,1650.68 5168.02,1650.68 ; 3420.36,456.12 3420.36,1800 ; 3777.36,456.12 3777.36,1800 ; 4438.93,456.12 4438.93,1800 ; 4723.07,456.12 4723.07,1800 ; 3050,456.12 5168.02,456.12 5168.02,1800 3050,1800 3050,456.12
  text "Symbol" at 3139.59,1695.48 h72
  text "Quantity" at 3465.16,1695.48 h72
  text "Finished Hole Size" at 3822.16,1695.48 h72
  text "Plated" at 4483.72,1695.48 h72
  text "Hole Type" at 4767.86,1695.48 h72
  text "29" at 3465.16,1546.16 h60
  text "7.87mil (0.200mm)" at 3822.16,1546.16 h60
  text "PTH" at 4483.72,1546.16 h60
  text "Round" at 4767.86,1546.16 h60
  text "11" at 3465.16,1396.84 h60
  text "10.00mil (0.254mm)" at 3822.16,1396.84 h60
  text "PTH" at 4483.72,1396.84 h60
  text "Round" at 4767.86,1396.84 h60
  text "267" at 3465.16,1247.52 h60
  text "12.00mil (0.305mm)" at 3822.16,1247.52 h60
  text "PTH" at 4483.72,1247.52 h60
  text "Round" at 4767.86,1247.52 h60
  text "5" at 3465.16,1098.2 h60
  text "40.16mil (1.020mm)" at 3822.16,1098.2 h60
  text "PTH" at 4483.72,1098.2 h60
  text "Round" at 4767.86,1098.2 h60
  text "40" at 3465.16,948.88 h60
  text "47.24mil (1.200mm)" at 3822.16,948.88 h60
  text "PTH" at 4483.72,948.88 h60
  text "Round" at 4767.86,948.88 h60
  text "5" at 3465.16,799.56 h60
  text "55.12mil (1.400mm)" at 3822.16,799.56 h60
  text "PTH" at 4483.72,799.56 h60
  text "Round" at 4767.86,799.56 h60
  text "3" at 3465.16,650.24 h60
  text "63.00mil (1.600mm)" at 3822.16,650.24 h60
  text "PTH" at 4483.72,650.24 h60
  text "Round" at 4767.86,650.24 h60
  text "360 Total" at 3465.16,500.92 h60
  text ".Layer_Name" at 577,-858.49 h60

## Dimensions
0,-400 to 1000,-400 on M2 Board Dimensions
0,0 to 2500,1250 on M2 Board Dimensions
0,0 to 0,1250 on M2 Board Dimensions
